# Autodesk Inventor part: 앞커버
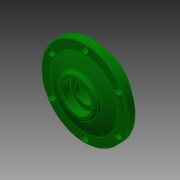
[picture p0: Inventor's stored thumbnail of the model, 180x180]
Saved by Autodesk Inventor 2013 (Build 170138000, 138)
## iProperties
Created: 2016-05
Part Number: 앞커버
Document SubType Name: Modeling
Designer: mduedu
Density: 2.71 g/cm^3
Material: 알루미늄 6061
Author: mduedu
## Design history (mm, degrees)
sketch "스케치1"
  geometry: C1 r 31 at (0, 0); C2 r 45 at (0, 0); 1 further point
  constraints: 2 centre point, 2 coincident
  dimensions: "d33" = 90 diameter of C2; "d34" = 62 diameter of C1
extrude "돌출1" new body sketch "스케치1" distance "d0" = 8; taper "d1" = 0 deg
extrude "돌출2" join sketch "스케치1" distance "d2" = 8; taper "d3" = 0 deg; dims "d35" = 12, "d36" = 0
sketch "스케치5"
  geometry: L1 (-45, 8)-(45, 8) reference; L2 (0, 0)-(0, 15); L3 (-45, 0)-(45, 0) reference; L4 (35, 8)-(0, 8); A1 r 91 centre (0, -76) between (35, 8) and (0, 15)
  constraints: 4 end point, 3 point on line, 2 point on circle, 1 centre point, 1 midpoint, 1 perpendicular
  dimensions: "d37" = 35 distance from line of L2 L4.start; "d39" = 7 distance from line of L1 L2.end
revolve "회전2" sketch "스케치5" stored, may be unused: angle "d40" = 90 deg
node "작업 평면1"
sketch "스케치6"
  geometry: C1 r 20 at (0, 0); 1 further point
  constraints: 1 centre point, 1 coincident
  dimensions: "d42" = 40 diameter of C1
extrude "돌출4" join sketch "스케치6" stored distance "d43" = 10; taper "d44" = 0 deg
sketch "스케치4"
  geometry: L1 (0, -12)-(0, 16); L2 (-20, -12)-(-20, 0); L3 (-20, 0)-(-15, 0); L4 (-15, 0)-(-15, 3); L5 (-15, 3)-(-10, 3); L6 (-10, 3)-(-10, 7.5); L7 (-10, 7.5)-(-15, 7.5); L8 (-15, 7.5)-(-15, 16); L9 (31, -12)-(-31, -12) reference; L10 (-20, 16)-(20, 16) reference; 1 further point
  constraints: 16 end point, 6 parallel, 3 point on line, 2 midpoint, 1 perpendicular, 1 vertical
  dimensions: "d15" = 40 diameter of L2 L1; "d16" = 30 diameter of L8 L1; "d18" = 12 distance of L2.start L2.end; "d19" = 3 distance of L3.end L4.end; "d20" = 30 diameter of L4 L1; "d21" = 20 diameter of L6 L1; "d45" = 8.5 distance of L7.end L8.end
revolve "회전1" sketch "스케치4" stored, may be unused: angle "d22" = 90 deg
fillet "모깎기2" dims "d23" = 3
fillet "모깎기3" dims "d24" = 0.3
chamfer "모따기2" distance "d46" = 1; stored, may be unused: second distance "d47" = 2, angle "d48" = 45 deg
fillet "모깎기4" dims "d49" = 3
fillet "모깎기5" dims "d50" = 3
fillet "모깎기6" dims "d51" = 1
sketch "스케치7" dims "d52" = 80
  geometry: C1 r 35.595 at (0, 0) reference; C2 r 44 at (0, 0) reference; 7 further points
  constraints: 2 vertical alignment, 1 coincident, 9 other
  dimensions: "d55" = 360 deg dimension on C1.centre point (0, 40) (derived)
sketch "스케치8"
  geometry: 6 further points
  constraints: 6 other
hole "구멍2" sketch "스케치8" at (-34.641, 20), (-34.641, -20), (0, -40), (34.641, -20), (34.641, 20), (0, 40) diameter "d57" = 4.5; stored, may be unused: countersink angle "d61" = 90 deg, drill point angle "d63" = 0 deg; dims "d58" = 6, "d59" = 8, "d60" = 4.6, "d62" = 8
chamfer "모따기3" distance "d64" = 0.8; stored, may be unused: second distance "d65" = 2, angle "d66" = 30 deg
node "솔리드1"
other parameters: "d41" = 8
